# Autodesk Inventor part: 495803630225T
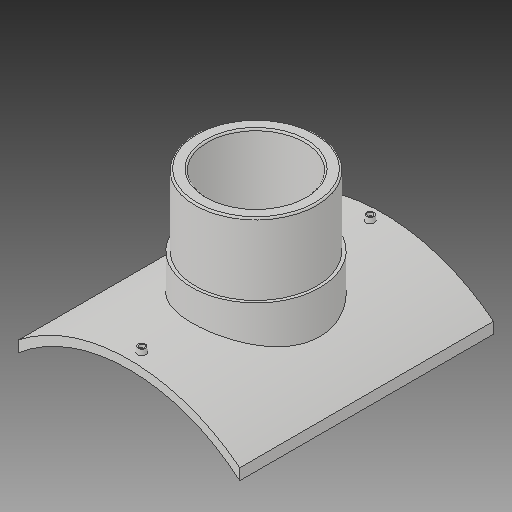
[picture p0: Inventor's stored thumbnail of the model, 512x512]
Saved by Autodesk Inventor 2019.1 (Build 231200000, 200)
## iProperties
Created: 2017-10
Part Number: 495803630225T
Material: Generic
Description: PLASSON BRANCH SADDLE  630x225
Document SubType Name: Modeling
Designer: KIM
Mass: 2754.05 g
Surface Area: 3037.44 cm^2
Volume: 2754.05 cm^3
Density: 1 g/cm^3
Appearance: Default
Author: KIM
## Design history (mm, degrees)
derived "495803.ipt"
feature "Solid1::495803.ipt"
tag "TaggingFeature1"
body "Solid1"
other parameters: "d1" = 16, "d4" = 0, "d12" = 340.6, "d13" = 14, "d14" = 211.5, "d16" = 5 deg, "d18" = 4, "d19" = 14, "d20" = 0, "d21" = 3, "d22" = 0, "d24" = 236.25, "d25" = 16, "d28" = 0, "d29" = 9.6, "d31" = 0, "d32" = 94.5, "d33" = 0, "d34" = 6.3, "d36" = 225, "d37" = 132.3, "d38" = 0, "d39" = 3.15, "d_1" = 225, "H_" = 189, "x_" = 16, "D_" = 16
